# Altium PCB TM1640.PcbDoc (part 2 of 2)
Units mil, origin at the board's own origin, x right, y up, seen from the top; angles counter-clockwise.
Board outline 3858.42 x 1968.54 mil, 2 copper layers (Top Layer, Bottom Layer); 104 components, 33 nets, 245 pads, 113 vias.
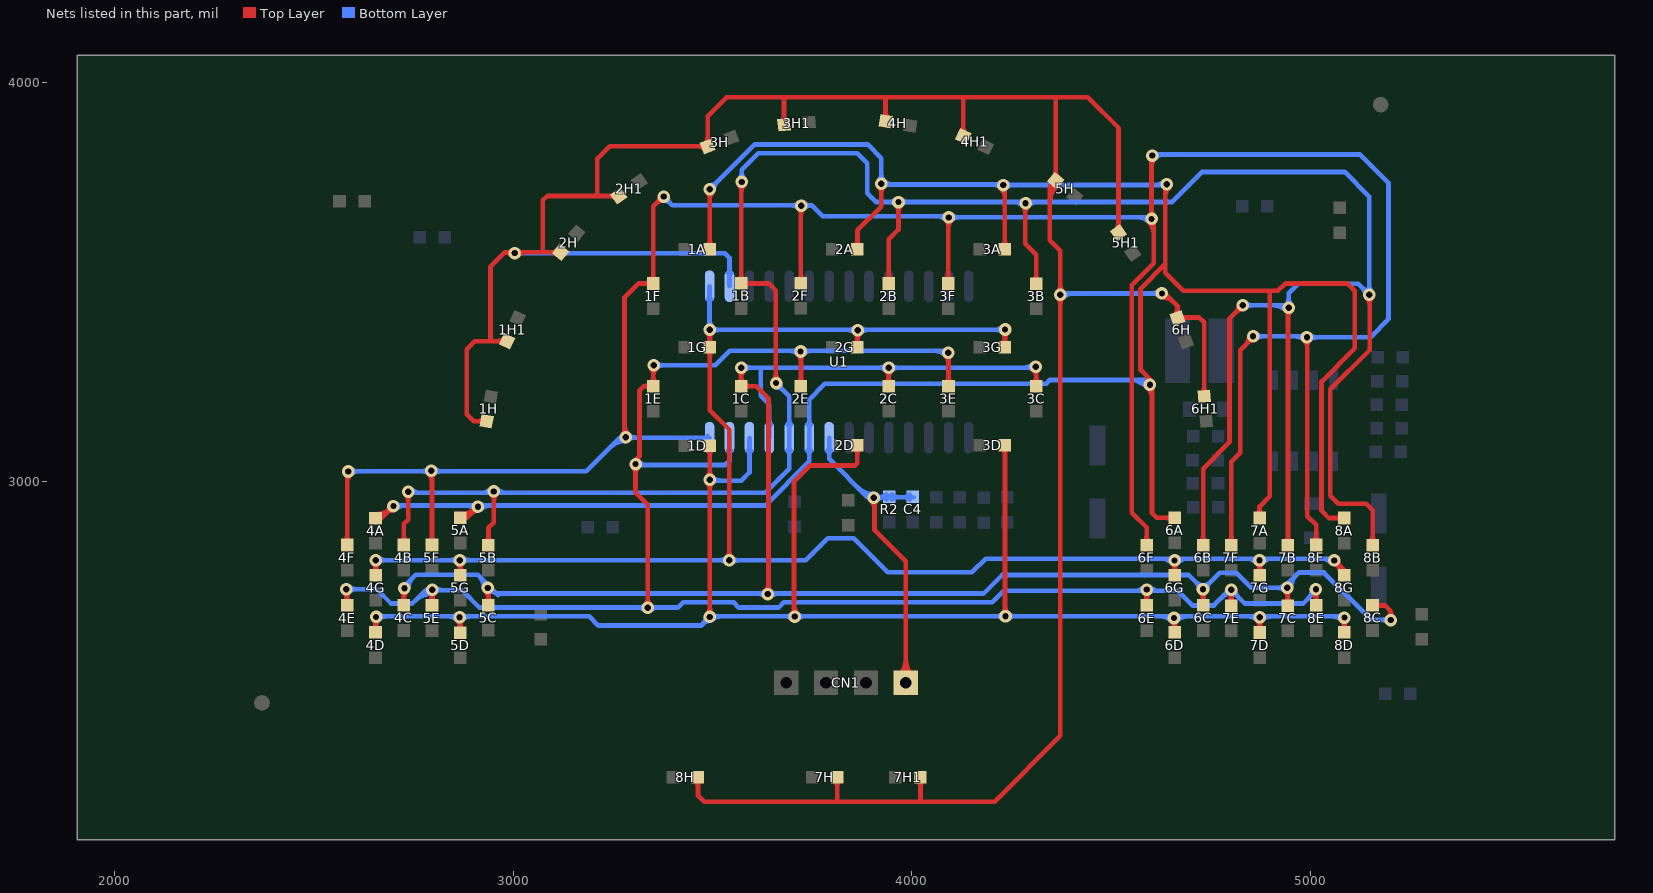
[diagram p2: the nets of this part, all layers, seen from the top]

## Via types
v1: diameter 31.5, hole 15.75, Top Layer to Bottom Layer, 113 vias

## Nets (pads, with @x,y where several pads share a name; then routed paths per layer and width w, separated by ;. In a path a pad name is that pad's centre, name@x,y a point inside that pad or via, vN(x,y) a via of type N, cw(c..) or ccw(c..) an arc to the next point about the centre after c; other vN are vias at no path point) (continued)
SCLK: C4.2 CN1.4 R2.1 U1.8 | length 1248.2
  Top Layer w11.81: v1@3897.21,2951.86 cw(c3875.75,2930.4) 3906.1,2930.4 ; 3906.1,2939.71 cw(c3923.28,2939.71) v1@3911.13,2951.86 ; v1@3906.1,2966.97 3906.1,2877.56 3984.44,2799.22 CN1.4@3984.44,2494.68 ; CN1.4@3967.18,2511.94 ccw(c3925.51,2553.61) 3984.44,2553.61 ccw(c4043.37,2553.61) CN1.4@4001.7,2511.94 ; CN1.4@3975.53,2503.59 ccw(c3954.03,2525.09) 3984.44,2525.09 ccw(c4014.86,2525.09) CN1.4@3993.35,2503.59
  Bottom Layer w11.81: U1.8@3787.82,3077.37 cw(c3777.41,3066.97) 3792.12,3066.97 ; 3792.13,3066.97 cw(c3806.84,3066.97) U1.8@3796.44,3077.37 ; U1.8@3792.13,3109.68 3792.13,3056.3 3888.15,2960.28 ; 3862.5,2985.92 ccw(c3904.17,3027.59) v1@3904.17,2968.66 ; 3882.67,2965.76 ccw(c3904.17,2987.26) v1@3904.17,2956.85 ; 3888.15,2960.27 cw(c3888.15,2953.11) v1@3894.9,2955.51 ; v1@3896.08,2964.43 cw(c3888.15,2969.93) 3888.15,2960.28 ; v1@3911.13,2951.86 cw(c3931.45,2931.54) R2.1@3931.45,2960.28 ; v1@3911.13,2965.78 ccw(c3924.42,2979.06) 3924.42,2960.28 ; v1@3916.93,2960.28 ccw(c3916.93,2987.13) R2.1@3935.91,2968.14 ; 3921.3,2960.27 cw(c3921.3,2939.6) R2.1@3935.91,2954.22 ; R2.1@3949.83,2954.22 cw(c3964.45,2939.6) 3964.45,2960.27 ; R2.1@3949.83,2968.14 ccw(c3968.82,2987.13) 3968.82,2960.28 ; 3975.7,2960.28 ccw(c3975.7,2987.13) C4.2@3994.69,2968.14 ; 3980.08,2960.28 cw(c3980.08,2939.61) C4.2@3994.69,2954.22 ; C4.2@4004.05,2960.28 3888.15,2960.28
  other v1: 3904.17,2958.82
SEG1: 1A.1 2A.1 3A.1 4A.1 5A.1 6A.1 7A.1 8A.1 U1.9 | length 7747.7
  Top Layer w11.81: 4A.1@2654.05,2906.14 ccw(c2654.05,2937.51) 2676.23,2915.33 ; 4A.1@2654.05,2908.11 2669.01,2908.11 v1(2698.98,2938.07) ; 4A.1@2654.05,2917.95 ccw(c2654.05,2977.83) v1@2696.4,2935.49 ; v1@2689.13,2938.07 cw(c2665.37,2938.07) 2682.17,2921.27 cw(c2698.98,2904.47) v1@2698.98,2928.23 ; 5A.1@2866.26,2906.46 ccw(c2866.88,2940.95) 2891.28,2916.56 ; 5A.1@2866.3,2908.43 2883.15,2908.43 ; 5A.1@2866.48,2918.27 ccw(c2867.58,2979.58) v1(2910.94,2936.22) 2883.15,2908.43 ; 5A.1@2874.87,2903.59 cw(c2883.15,2898.92) 2883.15,2908.42 ; 5A.1@2874.87,2913.26 ccw(c2883.15,2917.93) 2883.15,2908.43 ; v1@2901.1,2936.22 cw(c2877.34,2936.22) 2894.14,2919.42 cw(c2910.94,2902.62) v1@2910.94,2926.38 ; 1A.1@3485.95,3589.4 ccw(c3469.15,3606.2) 3492.91,3606.2 ccw(c3516.68,3606.2) 1A.1@3499.87,3589.4 ; v1@3485.95,3726.03 cw(c3469.15,3709.23) 3492.91,3709.23 cw(c3516.68,3709.23) v1@3499.87,3726.03 ; 1A.1@3492.91,3582.44 v1@3492.91,3729.33 ; 2A.1@3856.19,3589.4 ccw(c3839.39,3606.2) 3863.15,3606.2 ccw(c3886.91,3606.2) 2A.1@3870.11,3589.4 ; 2A.1@3863.15,3582.44 3863.15,3629.64 3923.19,3689.68 v1(3923.19,3746.97) ; v1@3916.23,3740.01 cw(c3899.43,3723.21) 3923.19,3723.21 cw(c3946.95,3723.21) v1@3930.15,3740.01 ; v1@4222.33,3736.5 cw(c4196.78,3710.96) 4232.91,3710.96 ; 3A.1@4225.95,3589.16 ccw(c4209.15,3605.97) 4232.91,3605.97 ccw(c4256.68,3605.97) 3A.1@4239.87,3589.16 ; 3A.1@4232.91,3582.2 v1@4232.91,3739.84 ; v1@4590.09,3235.8 cw(c4561.31,3207.02) 4602.01,3207.02 ; v1@4602.01,3242.76 4602.01,2921.06 4614.45,2908.62 6A.1@4659.65,2908.62 6A.1@4664.53,2903.74 ; v1@4602.01,3250.94 4573.39,3279.57 4573.39,3483.66 4635.24,3545.51 ; 4635.24,3712.43 cw(c4672.57,3712.43) v1@4646.17,3738.83 ; v1@4635.24,3744.33 4635.24,3545.51 ; 6A.1@4652.68,2901.66 ccw(c4635.88,2884.86) 4635.88,2908.62 ccw(c4635.88,2932.38) 6A.1@4652.68,2915.58 ; 7A.1@4865.05,2915.19 ccw(c4848.24,2931.99) 4872.01,2931.99 ccw(c4895.77,2931.99) 7A.1@4878.97,2915.19 ; 7A.1@4872.01,2908.23 4872.01,2936.81 4897.8,2962.6 4897.8,3478.35 ; 8A.1@5078,2901.27 ccw(c5061.2,2884.47) 5061.2,2908.23 ccw(c5061.2,2931.99) 8A.1@5078,2915.19 ; 8A.1@5084.96,2908.23 5045.63,2908.23 5027.56,2926.3 5027.56,3250.51 5111.1,3334.05 5111.1,3478.54 5093.19,3496.46 4936.26,3496.46 4918.15,3478.35 4897.8,3478.35 ; 4635.24,3545.51 4635.24,3523.7 4680.59,3478.35 4897.8,3478.35
  Bottom Layer w11.81: v1@2697.83,2939.53 3631.3,2939.53 3742.13,3050.35 U1.9@3742.13,3109.68 3742.13,3205.16 3781.65,3244.68 4336.26,3244.68 4346.06,3254.49 4585.31,3254.49 ; v1@2705.94,2931.11 cw(c2726.26,2910.79) 2726.26,2939.53 ; v1@2705.94,2945.03 ccw(c2719.22,2958.32) 2719.22,2939.53 ; 2879.2,2939.53 cw(c2879.2,2904.47) v1@2903.98,2929.26 ; 2895.17,2939.53 ccw(c2895.17,2952) v1@2903.98,2943.18 ; v1@2917.9,2929.26 cw(c2942.69,2904.47) 2942.69,2939.53 ; v1@2917.9,2943.18 ccw(c2926.72,2952) 2926.72,2939.53 ; v1(3492.91,3732.99) 3605.39,3845.47 3888.43,3845.47 3923.19,3810.71 v1@3923.19,3749.41 ; v1@3492.91,3742.84 ccw(c3492.91,3766.6) 3509.71,3749.79 ccw(c3526.52,3732.99) v1@3502.76,3732.99 ; U1.9@3737.82,3077.37 cw(c3727.41,3066.97) 3742.12,3066.97 ; U1.9@3737.82,3141.99 ccw(c3727.41,3152.4) 3742.12,3152.4 ; 3742.13,3066.97 cw(c3756.84,3066.97) U1.9@3746.44,3077.37 ; 3742.13,3152.4 ccw(c3756.84,3152.4) U1.9@3746.44,3141.99 ; v1@3916.23,3753.93 ccw(c3899.43,3770.73) 3923.19,3770.73 ccw(c3946.95,3770.73) 3930.15,3753.93 ccw(c3951.89,3775.67) 3951.89,3744.92 ; v1@3927.68,3744.92 v1@4229.29,3744.92 ; v1@3930.15,3740.01 cw(c3942.01,3728.15) 3942.01,3744.92 ; 4202.01,3744.92 cw(c4202.01,3716.18) v1@4222.33,3736.5 ; 4209.05,3744.92 ccw(c4209.05,3763.71) v1@4222.33,3750.42 ; v1(4229.29,3743.46) v1@4628.98,3743.46 ; v1@4236.25,3736.5 cw(c4253.05,3719.7) 4253.05,3743.46 cw(c4253.05,3767.23) v1@4236.25,3750.42 ; 4544.96,3254.49 cw(c4544.96,3190.67) v1@4590.09,3235.8 ; 4573.48,3254.49 cw(c4573.48,3219.18) v1@4598.44,3244.15 ; 4609.84,3743.47 ccw(c4609.84,3775.16) v1@4632.25,3752.75 ; 4621.06,3743.46 cw(c4621.06,3727.63) v1@4632.25,3738.83
  other v1: 4597.05,3242.76 4639.21,3745.79
SEG2: 1B.1 2B.1 3B.1 4B.1 5B.1 6B.1 7B.1 8B.1 U1.10 | length 8107.5
  Top Layer w11.81: 4B.1@2718.08,2847.43 ccw(c2701.28,2864.23) 2725.04,2864.23 ccw(c2748.8,2864.23) 4B.1@2732,2847.43 ; 4B.1@2725.04,2840.47 2725.04,2893.46 2735.98,2904.41 v1(2735.98,2974.29) ; v1@2729.02,2967.33 cw(c2712.22,2950.53) 2735.98,2950.53 cw(c2759.75,2950.53) v1@2742.94,2967.33 ; 5B.1@2930.48,2847.24 ccw(c2913.68,2864.04) 2937.44,2864.04 ccw(c2961.2,2864.04) 5B.1@2944.4,2847.24 ; 5B.1@2937.44,2840.28 2937.44,2883.43 2950.91,2896.89 v1(2950.91,2974.88) ; v1@2943.94,2967.92 cw(c2927.14,2951.12) 2950.9,2951.12 cw(c2974.67,2951.12) v1@2957.87,2967.92 ; 1B.1@3564.73,3503.73 ccw(c3547.93,3520.53) 3571.69,3520.53 ccw(c3595.45,3520.53) 3578.65,3503.73 ccw(c3595.45,3520.53) 3595.45,3496.77 ccw(c3595.45,3473.01) 1B.1@3578.65,3489.81 ; v1@3565.95,3744.46 cw(c3552.1,3730.6) 3571.69,3730.6 ; 3571.69,3724.71 cw(c3599.62,3724.71) v1@3579.87,3744.46 ; v1@3571.69,3753.46 1B.1@3571.69,3496.77 3640.08,3496.77 3657.87,3478.98 v1@3657.87,3246.1 ; v1@3651.94,3253.65 ccw(c3637.61,3267.98) 3657.87,3267.98 ; 3657.87,3272.93 ccw(c3685.13,3272.93) v1@3665.86,3253.65 ; 2B.1@3934.85,3503.46 ccw(c3918.05,3520.26) 3941.81,3520.26 ccw(c3965.57,3520.26) 2B.1@3948.77,3503.46 ; 2B.1@3941.81,3496.5 3941.81,3607.83 3966.14,3632.16 v1(3966.14,3700.87) ; v1@3959.18,3693.91 cw(c3942.38,3677.1) 3966.14,3677.1 cw(c3989.9,3677.1) v1@3973.1,3693.91 ; v1@4278.04,3691.03 cw(c4263.71,3676.7) 4283.97,3676.7 ; 4283.98,3671.76 cw(c4311.23,3671.76) v1@4291.96,3691.03 ; v1@4283.98,3698.54 4283.98,3596.85 4311.73,3569.09 3B.1@4311.73,3496.46 ; 3B.1@4304.77,3503.42 ccw(c4287.97,3520.22) 4311.73,3520.22 ccw(c4335.49,3520.22) 3B.1@4318.69,3503.42 ; 6B.1@4723.47,2847.2 ccw(c4706.67,2864) 4730.43,2864 ccw(c4754.19,2864) 6B.1@4737.39,2847.2 ; 6B.1@4730.43,2840.24 4730.43,3032.12 4796.53,3098.23 4796.53,3408.46 v1@4832.24,3444.17 ; 4812.74,3424.67 ccw(c4795.6,3441.81) v1@4819.84,3441.81 ; 4813.22,3425.15 cw(c4829.69,3408.68) v1@4829.69,3431.97 ; 7B.1@4936.15,2847.12 ccw(c4919.35,2863.92) 4943.11,2863.92 ccw(c4966.87,2863.92) 7B.1@4950.07,2847.12 ; v1@4938.04,3428.51 cw(c4925.8,3416.27) 4943.11,3416.27 ; 7B.1@4943.11,2840.16 v1@4943.11,3433.58 ; 4943.11,3407.15 cw(c4973.32,3407.15) v1@4951.96,3428.51 ; v1@5140.24,3461.27 cw(c5121.26,3442.28) 5148.11,3442.28 ; 5148.11,3446.65 cw(c5168.78,3446.65) v1@5154.16,3461.27 ; v1@5148.11,3467.36 5148.11,3329.72 5049.37,3230.98 5049.37,2964.49 5069.92,2943.94 5140,2943.94 5155.71,2928.23 8B.1@5155.71,2840.28 ; 8B.1@5148.75,2847.24 ccw(c5131.95,2864.04) 5155.71,2864.04 ccw(c5179.47,2864.04) 8B.1@5162.67,2847.24
  Bottom Layer w11.81: v1@2736.69,2971.38 3632.3,2971.38 3692.13,3031.2 U1.10@3692.13,3109.68 3692.13,3213.46 v1(3658.9,3246.69) ; v1@2742.94,2967.33 cw(c2752.71,2957.56) 2752.71,2971.38 ; v1@2742.94,2981.25 ccw(c2766.78,3005.09) 2766.78,2971.38 ; 2918.68,2971.38 ccw(c2918.68,3007.1) v1@2943.95,2981.84 ; v1@2957.86,2981.84 ccw(c2983.13,3007.1) 2983.13,2971.38 ; v1@3565.95,3758.38 ccw(c3549.15,3775.18) 3572.91,3775.18 ccw(c3596.68,3775.18) v1@3579.87,3758.38 ; v1(3572.91,3751.42) 3572.91,3782.15 3614.43,3823.66 3862.64,3823.66 3887.87,3798.43 3887.87,3722.91 3909.92,3700.87 v1(3966.14,3700.87) 4652.24,3700.87 4727.72,3776.34 5085.47,3776.34 5147.2,3714.61 v1(5147.2,3468.23) 5119.33,3496.1 4968.58,3496.1 4945,3472.52 v1(4945,3435.47) ; v1@3658.9,3236.85 cw(c3658.9,3213.09) 3675.7,3229.89 cw(c3692.5,3246.69) v1@3668.74,3246.69 ; U1.10@3687.82,3077.37 cw(c3677.41,3066.97) 3692.12,3066.97 ; U1.10@3687.82,3141.99 ccw(c3677.41,3152.4) 3692.12,3152.4 ; 3692.13,3066.97 cw(c3706.84,3066.97) U1.10@3696.44,3077.37 ; 3692.13,3152.4 ccw(c3706.84,3152.4) U1.10@3696.44,3141.99 ; v1@3959.18,3693.91 ccw(c3942.38,3677.1) 3942.38,3700.86 ccw(c3942.38,3724.63) v1@3959.18,3707.83 ; v1@3973.1,3693.91 cw(c3989.9,3677.1) 3989.9,3700.86 cw(c3989.9,3724.63) v1@3973.1,3707.83 ; 4254.3,3700.87 cw(c4254.3,3667.29) v1@4278.04,3691.03 ; 4268.18,3700.87 ccw(c4268.18,3714.82) v1@4278.04,3704.95 ; v1@4291.96,3691.03 cw(c4315.7,3667.29) 4315.7,3700.87 ; v1@4291.96,3704.95 ccw(c4301.82,3714.82) 4301.82,3700.87 ; v1(4829.69,3441.81) v1@4943.98,3441.81 ; v1@4836.65,3434.85 cw(c4853.45,3418.05) 4853.45,3441.81 cw(c4853.45,3465.57) v1@4836.65,3448.77 ; 4905.94,3441.81 cw(c4905.94,3396.41) v1@4938.04,3428.51 ; v1@4938.04,3442.43 ccw(c4921.24,3459.23) 4945,3459.23 ccw(c4968.76,3459.23) v1@4951.96,3442.43 ; v1@5137.36,3468.23 ccw(c5113.6,3468.23) 5130.4,3485.03 ccw(c5147.2,3501.83) v1@5147.2,3478.07 ; v1@5140.24,3475.19 ccw(c5123.44,3491.99) 5147.2,3491.99 ccw(c5170.97,3491.99) v1@5154.16,3475.19
  other v1: 4285,3697.99
SEG3: 1C.1 2C.1 3C.1 4C.1 5C.1 6C.1 7C.1 8C.1 U1.11 | length 5695.8
  Top Layer w11.81: 4C.1@2717.72,2695.86 ccw(c2700.92,2712.66) 2724.68,2712.66 ccw(c2748.45,2712.66) 4C.1@2731.64,2695.86 ; v1@2719.58,2724.81 cw(c2707.24,2712.48) 2724.68,2712.48 ; 4C.1@2724.68,2688.9 v1@2724.68,2729.92 ; 4C.1@2724.68,2703.54 cw(c2754.76,2703.54) v1@2733.5,2724.81 ; v1@2928.9,2725.72 cw(c2908.3,2705.11) 2937.44,2705.11 ; 5C.1@2930.48,2696.02 ccw(c2913.68,2712.82) 2937.44,2712.82 ccw(c2961.2,2712.82) 5C.1@2944.4,2696.02 ; 5C.1@2937.44,2689.05 v1@2937.44,2731.1 ; 2937.44,2712.72 cw(c2955.83,2712.72) v1@2942.83,2725.72 ; 1C.1@3564.5,3245.86 ccw(c3547.69,3262.66) 3571.45,3262.66 ccw(c3595.22,3262.66) 3578.42,3245.86 ccw(c3595.22,3262.66) 3595.22,3238.9 ccw(c3595.22,3215.14) 1C.1@3578.42,3231.94 ; v1@3564.81,3278.39 cw(c3548.77,3262.35) 3571.46,3262.35 ; 3571.46,3260.83 cw(c3596.29,3260.83) v1@3578.73,3278.39 ; v1@3571.46,3281.97 1C.1@3571.46,3238.9 3608.9,3238.9 3640.24,3207.56 v1@3640.24,2723.15 ; v1@3631.39,2724.28 ccw(c3610.02,2745.65) 3640.24,2745.65 ; 3640.24,2736.52 ccw(c3657.55,2736.52) v1@3645.31,2724.28 ; v1@3934.46,3277.96 cw(c3917.37,3260.87) 3941.53,3260.87 ; 2C.1@3934.57,3245.74 ccw(c3917.77,3262.54) 3941.53,3262.54 ccw(c3965.3,3262.54) 2C.1@3948.5,3245.74 ; 2C.1@3941.53,3238.78 v1@3941.53,3284.8 ; 3941.53,3261.44 cw(c3964.89,3261.44) v1@3948.38,3277.96 ; v1@4303.2,3280.6 cw(c4282.31,3259.71) 4311.85,3259.71 ; 3C.1@4304.89,3245.86 ccw(c4288.09,3262.66) 4311.85,3262.66 ccw(c4335.61,3262.66) 3C.1@4318.81,3245.86 ; 3C.1@4311.85,3238.9 v1@4311.85,3285.87 ; 4311.85,3267.88 cw(c4329.83,3267.88) v1@4317.12,3280.6 ; v1@4723.2,2722.25 cw(c4705.92,2704.97) 4730.35,2704.97 ; 6C.1@4723.39,2695.86 ccw(c4706.59,2712.66) 4730.35,2712.66 ccw(c4754.12,2712.66) 6C.1@4737.31,2695.86 ; 6C.1@4730.35,2688.9 v1@4730.35,2723.11 ; 4730.35,2705.93 cw(c4753.44,2705.93) v1@4737.12,2722.25 ; v1@4934.3,2726.15 cw(c4913.79,2705.64) 4942.79,2705.64 ; 7C.1@4935.83,2695.54 ccw(c4919.03,2712.34) 4942.79,2712.34 ccw(c4966.56,2712.34) 7C.1@4949.76,2695.54 ; 7C.1@4942.8,2688.58 v1@4942.8,2733.07 ; 4942.79,2713.05 cw(c4961.31,2713.05) v1@4948.22,2726.15 ; 8C.1@5155.39,2688.9 5186.69,2688.9 5201.14,2674.45 ; 8C.1@5162.35,2681.94 cw(c5179.15,2665.14) 5179.15,2688.9 cw(c5179.15,2712.66) 8C.1@5162.35,2695.86 ; v1@5194.53,2659.54 ccw(c5181.02,2674.45) 5201.14,2674.45 ; v1(5201.14,2652.24) 5201.14,2674.45 ; v1@5207.75,2659.54 cw(c5221.26,2674.45) 5201.14,2674.45
  Bottom Layer w11.81: v1@2723.9,2734.41 2755.59,2766.1 2910.59,2766.1 2957.91,2718.78 4179.49,2718.78 4225.94,2765.24 4694.13,2765.24 v1(4730.16,2729.21) 4771.85,2770.91 4813.35,2770.91 4851.14,2733.11 v1(4941.26,2733.11) ; v1@2736.38,2731.77 cw(c2772.88,2731.77) 2747.07,2757.58 ; 2913.3,2763.39 cw(c2882.59,2732.68) v1@2926.02,2732.68 ; v1@2937.27,2722.93 cw(c2941.41,2694.12) 2961.99,2714.71 ; v1(3571.77,3285.35) 3620.55,3285.35 ; v1@3578.73,3278.39 cw(c3595.53,3261.59) 3595.53,3285.35 cw(c3595.53,3309.12) v1@3578.73,3292.31 ; 3611.07,2718.78 cw(c3611.07,2690.04) v1@3631.39,2710.36 ; 3618.1,2718.78 ccw(c3618.1,2737.57) v1@3631.39,2724.28 ; U1.11@3637.82,3141.99 ccw(c3627.41,3152.4) 3642.12,3152.4 ; U1.11@3642.13,3109.68 3642.13,3193.39 3620.55,3214.96 3620.55,3285.35 ; 3642.13,3152.4 ccw(c3656.84,3152.4) U1.11@3646.44,3141.99 ; v1@3645.31,2710.36 cw(c3665.62,2690.04) 3665.62,2718.78 ; v1@3645.31,2724.28 ccw(c3658.59,2737.57) 3658.59,2718.78 ; 3916.61,3285.35 cw(c3916.61,3260.11) v1@3934.46,3277.96 ; 3918.7,3285.35 ccw(c3918.7,3307.64) v1@3934.46,3291.88 ; v1@3948.38,3277.96 cw(c3966.22,3260.11) 3966.22,3285.35 ; v1@3948.38,3291.88 ccw(c3964.13,3307.64) 3964.13,3285.35 ; 4281.07,3285.35 ccw(c4281.07,3316.64) v1@4303.2,3294.52 ; 4291.72,3285.35 cw(c4291.72,3269.12) v1@4303.2,3280.6 ; v1@4309.25,3285.35 3620.55,3285.35 ; v1@4720.31,2729.21 ccw(c4696.55,2729.21) 4713.35,2746.01 ccw(c4730.16,2762.82) 4730.16,2739.06 ccw(c4730.16,2762.82) 4746.96,2746.02 ccw(c4763.76,2729.21) v1@4740,2729.21 ; v1@4934.3,2726.15 ccw(c4917.5,2709.35) 4917.5,2733.11 ccw(c4917.5,2756.87) v1@4934.3,2740.07 ; v1@4936.48,2737.89 4969.96,2771.38 5033.5,2771.38 5151.85,2653.03 v1@5201.14,2653.03 ; v1@4951.1,2733.11 cw(c4997.96,2733.11) 4964.83,2766.24 ; 5175.48,2653.03 cw(c5175.48,2626.58) v1@5194.18,2645.28 ; 5179.28,2653.03 ccw(c5179.28,2674.11) v1@5194.18,2659.2
  other v1: 3638.35,2717.32 2726.53,2731.77 2935.87,2732.68 3941.42,3284.92 4310.16,3287.56
SEG4: 1D.1 2D.1 3D.1 4D.1 5D.1 6D.1 7D.1 8D.1 U1.12 | length 5477.5
  Top Layer w11.81: 4D.1@2647.09,2627.98 ccw(c2630.29,2644.78) 2654.05,2644.78 ccw(c2677.82,2644.78) 4D.1@2661.01,2627.98 ; v1@2648.47,2653.08 cw(c2635,2639.6) 2654.05,2639.6 ; 4D.1@2654.05,2621.02 v1@2654.05,2658.66 ; 4D.1@2654.05,2632.95 cw(c2682.52,2632.95) v1@2662.39,2653.08 ; v1@2857.88,2652.25 cw(c2836.42,2630.79) 5D.1@2866.77,2630.79 ; 5D.1@2859.81,2627.79 ccw(c2843.01,2644.59) 2866.77,2644.59 ccw(c2890.53,2644.59) 5D.1@2873.73,2627.79 ; 5D.1@2866.77,2620.83 v1@2866.77,2657.28 ; 2866.77,2640.11 cw(c2883.95,2640.11) v1@2871.8,2652.25 ; v1@3485.68,2667 ccw(c3468.59,2684.09) 3492.76,2684.09 ; v1@3485.68,2997.05 cw(c3468.59,2979.97) 3492.76,2979.97 ; v1@3485.68,3010.98 ccw(c3468.59,3028.06) 3492.76,3028.06 ; 1D.1@3485.8,3083.04 cw(c3468.99,3066.24) 3492.76,3066.24 cw(c3516.52,3066.24) 1D.1@3499.72,3083.04 ; v1@3492.76,2661.14 1D.1@3492.76,3090 ; 3492.76,2683.52 ccw(c3516.11,2683.52) v1@3499.6,2667 ; 3492.76,2980.54 cw(c3516.11,2980.54) v1@3499.6,2997.06 ; 3492.76,3027.49 ccw(c3516.11,3027.49) v1@3499.6,3010.97 ; v1@3699.18,2667.83 ccw(c3687.7,2679.3) 3703.94,2679.3 ; v1@3703.94,2660.98 3703.94,2999.64 3743.98,3039.68 3856.89,3039.68 3862.99,3045.79 2D.1@3862.99,3090.43 ; 3703.94,2689.95 ccw(c3735.23,2689.95) v1@3713.1,2667.83 ; 2D.1@3856.03,3083.47 cw(c3839.23,3066.67) 3862.99,3066.67 cw(c3886.75,3066.67) 2D.1@3869.95,3083.47 ; 3D.1@4226.15,3083.31 cw(c4209.35,3066.51) 4233.11,3066.51 cw(c4256.87,3066.51) 3D.1@4240.07,3083.31 ; v1@4227.65,2668.65 ccw(c4214.46,2681.84) 4233.11,2681.84 ; v1@4233.11,2663.54 3D.1@4233.11,3090.28 ; 4233.11,2689.07 ccw(c4261.98,2689.07) v1@4241.57,2668.65 ; v1@4650.4,2650.36 cw(c4628.56,2628.52) 6D.1@4659.45,2628.52 ; 6D.1@4652.49,2627.98 ccw(c4635.69,2644.78) 4659.45,2644.78 ccw(c4683.21,2644.78) 6D.1@4666.41,2627.98 ; 6D.1@4659.45,2621.02 v1@4659.45,2655.24 ; 4659.45,2638.6 cw(c4676.09,2638.6) v1@4664.32,2650.36 ; 7D.1@4865.28,2627.9 ccw(c4848.48,2644.71) 4872.24,2644.71 ccw(c4896.01,2644.71) 7D.1@4879.2,2627.9 ; v1@4865.28,2652.25 cw(c4848.48,2635.45) 4872.24,2635.45 cw(c4896.01,2635.45) v1@4879.2,2652.25 ; 7D.1@4872.24,2620.94 v1(4872.24,2659.21) ; 8D.1@5077.72,2627.98 ccw(c5060.92,2644.78) 5084.68,2644.78 ccw(c5108.45,2644.78) 8D.1@5091.64,2627.98 ; v1@5077.96,2651.46 cw(c5061.73,2635.23) 8D.1@5084.68,2635.23 ; 8D.1@5084.68,2621.02 v1@5084.68,2658.19 ; 8D.1@5084.68,2634.09 cw(c5109.25,2634.09) v1@5091.88,2651.46
  Bottom Layer w11.81: v1@2656.81,2661.69 3189.88,2661.69 3213.15,2638.43 3471.02,2638.43 v1(3492.64,2660.04) ; v1@2662.39,2653.08 cw(c2683.19,2632.28) 2683.19,2661.69 ; v1@2662.39,2667 ccw(c2675.2,2679.81) 2675.2,2661.69 ; 2835.09,2661.69 cw(c2835.09,2629.46) v1@2857.88,2652.25 ; 2847.07,2661.69 ccw(c2847.07,2676.99) v1@2857.88,2666.17 ; v1@2871.8,2652.25 cw(c2894.59,2629.46) 2894.59,2661.69 ; v1@2871.8,2666.17 ccw(c2882.62,2676.99) 2882.62,2661.69 ; v1@3482.79,2660.04 cw(c3459.03,2660.04) 3475.83,2643.24 cw(c3492.64,2626.43) v1@3492.64,2650.2 ; v1@3492.64,2661.69 v1(4234.61,2661.69) v1@5081.34,2661.69 ; v1@3495.35,3001.69 3571.46,3001.69 3592.13,3022.36 U1.12@3592.13,3109.68 ; v1@3499.6,2653.08 cw(c3520.39,2632.28) 3520.39,2661.69 ; v1@3499.6,2667 ccw(c3512.41,2679.81) 3512.41,2661.69 ; v1@3499.6,2997.06 cw(c3510.79,2985.86) 3510.79,3001.69 ; v1@3499.6,3010.98 ccw(c3522.01,3033.39) 3522.01,3001.69 ; U1.12@3587.82,3077.37 cw(c3577.41,3066.97) 3592.12,3066.97 ; 3592.13,3066.97 cw(c3606.84,3066.97) U1.12@3596.44,3077.37 ; 3680.38,2661.69 cw(c3680.38,2635.11) v1@3699.18,2653.91 ; 3684.38,2661.69 ccw(c3684.38,2682.63) v1@3699.18,2667.82 ; v1@3713.1,2653.91 cw(c3731.9,2635.11) 3731.9,2661.69 ; v1@3713.1,2667.82 ccw(c3727.91,2682.63) 3727.91,2661.69 ; v1@4227.65,2654.73 ccw(c4210.84,2637.93) 4210.84,2661.69 ccw(c4210.84,2685.45) v1@4227.65,2668.65 ; v1@4241.57,2654.73 cw(c4258.37,2637.93) 4258.37,2661.69 cw(c4258.37,2685.45) v1@4241.57,2668.65 ; 4623.05,2661.69 cw(c4623.05,2623.01) v1@4650.4,2650.36 ; v1@4664.32,2650.36 cw(c4691.67,2623.01) 4691.67,2661.69 ; 4842.49,2661.69 cw(c4842.49,2629.46) v1@4865.28,2652.25 ; 4854.47,2661.69 ccw(c4854.47,2676.99) v1@4865.28,2666.17 ; v1@4879.2,2652.25 cw(c4901.99,2629.46) 4901.99,2661.69 ; v1@4879.2,2666.17 ccw(c4890.02,2676.99) 4890.02,2661.69 ; 5053.27,2661.69 cw(c5053.27,2626.77) v1@5077.96,2651.46 ; 5069.05,2661.69 ccw(c5069.05,2674.3) v1@5077.96,2665.38
  other v1: 4657.36,2657.32 5084.92,2658.43 2864.84,2659.21 2655.43,2660.04 3706.14,2660.87 3492.64,3004.01
SEG5: 1E.1 2E.1 3E.1 4E.1 5E.1 6E.1 7E.1 8E.1 U1.13 | length 6010.4
  Top Layer w11.81: v1@2574.02,2722.61 cw(c2552.47,2701.05) 4E.1@2582.95,2701.05 ; 4E.1@2575.99,2695.78 ccw(c2559.19,2712.58) 2582.95,2712.58 ccw(c2606.71,2712.58) 4E.1@2589.91,2695.78 ; 4E.1@2582.95,2688.82 v1@2582.95,2732.09 ; 2582.95,2710.56 cw(c2599.99,2710.56) v1@2587.94,2722.61 ; 5E.1@2788.75,2695.78 ccw(c2771.95,2712.58) 2795.71,2712.58 ccw(c2819.47,2712.58) 5E.1@2802.67,2695.78 ; v1@2789.34,2721.35 cw(c2773.96,2705.97) 2795.71,2705.97 ; 5E.1@2795.71,2688.82 v1@2795.71,2727.72 ; 5E.1@2795.71,2703.12 cw(c2821.49,2703.12) v1@2803.26,2721.35 ; v1@3299.46,3036.46 cw(c3282.66,3019.66) 3306.42,3019.66 cw(c3330.18,3019.66) v1@3313.38,3036.46 ; v1@3301.5,3048.35 3316.26,3063.11 ; v1(3306.42,3043.43) 3306.42,2971.93 3337.09,2941.26 v1@3337.09,2693.31 ; v1@3314.7,3048.74 cw(c3324.41,3054.96) 3316.26,3063.11 ; v1@3330.05,2689.95 ccw(c3313.06,2706.94) 3337.09,2706.94 ; 3337.09,2706.56 ccw(c3360.58,2706.56) v1@3343.97,2689.95 ; 1E.1@3344.1,3232.05 ccw(c3327.3,3215.25) 3327.3,3239.01 ccw(c3327.3,3262.78) 3344.1,3245.98 ccw(c3327.3,3262.78) 3351.06,3262.78 ccw(c3374.82,3262.78) 1E.1@3358.02,3245.98 ; v1@3345.01,3284.18 cw(c3330.39,3269.57) 3351.06,3269.57 ; 3351.06,3265.19 cw(c3377.92,3265.19) v1@3358.93,3284.18 ; v1@3351.06,3296.26 1E.1@3351.06,3239.01 3327.24,3239.01 3316.26,3228.03 3316.26,3063.11 ; v1@3713.51,3318.94 cw(c3694.43,3299.86) 3721.42,3299.86 ; 2E.1@3714.46,3245.7 ccw(c3697.66,3262.5) 3721.42,3262.5 ccw(c3745.18,3262.5) 2E.1@3728.38,3245.7 ; 2E.1@3721.42,3238.74 v1@3721.42,3324.96 ; 3721.42,3304.42 cw(c3741.95,3304.42) v1@3727.43,3318.95 ; v1@4083.67,3316.07 cw(c4064.68,3297.08) 4091.53,3297.08 ; 3E.1@4084.57,3245.7 ccw(c4067.77,3262.5) 4091.53,3262.5 ccw(c4115.3,3262.5) 3E.1@4098.5,3245.7 ; 3E.1@4091.53,3238.74 v1@4091.53,3322.13 ; 4091.54,3301.45 cw(c4112.21,3301.45) v1@4097.59,3316.07 ; 6E.1@4581.78,2695.78 ccw(c4564.98,2712.58) 4588.74,2712.58 ccw(c4612.5,2712.58) 6E.1@4595.7,2695.78 ; v1@4582.25,2721.78 cw(c4566.59,2706.12) 4588.74,2706.12 ; 6E.1@4588.74,2688.82 v1@4588.74,2728.27 ; 6E.1@4588.74,2703.84 cw(c4614.11,2703.84) v1@4596.17,2721.78 ; v1@4793.71,2721.39 cw(c4775.29,2702.97) 7E.1@4801.34,2702.97 ; 7E.1@4794.38,2695.58 ccw(c4777.58,2712.38) 4801.34,2712.38 ccw(c4825.1,2712.38) 7E.1@4808.3,2695.58 ; 7E.1@4801.34,2688.62 v1@4801.34,2727.68 ; 4801.34,2706.2 cw(c4822.81,2706.2) v1@4807.63,2721.39 ; v1@5006.39,2722.61 cw(c4988.54,2704.76) 5013.78,2704.76 ; 8E.1@5006.82,2695.78 ccw(c4990.02,2712.58) 5013.78,2712.58 ccw(c5037.54,2712.58) 8E.1@5020.74,2695.78 ; 8E.1@5013.78,2688.82 v1@5013.78,2729.13 ; 5013.78,2706.85 cw(c5036.06,2706.85) v1@5020.31,2722.61
  Bottom Layer w11.81: v1(2580.98,2729.57) 2657.05,2729.57 2692.91,2693.7 2746.5,2693.7 2780.04,2727.24 ; v1@2587.94,2722.61 cw(c2604.75,2705.8) 2604.75,2729.57 cw(c2604.75,2753.33) v1@2587.94,2736.53 ; 2753.55,2700.76 cw(c2796.3,2658.01) v1@2796.3,2718.46 ; 2772.44,2719.64 cw(c2781.84,2710.25) v1@2790.15,2720.62 ; 2773.72,2720.92 cw(c2796.3,2698.34) v1@2796.3,2730.28 ; v1@2787.19,2732.04 cw(c2780.04,2734.97) 2780.04,2727.24 ; v1@2788.07,2722.91 ccw(c2780.04,2717.64) 2780.04,2727.24 ; v1@2803.26,2721.35 cw(c2817.49,2707.11) 2817.49,2727.24 ; v1@2803.26,2735.27 ccw(c2822.63,2754.64) 2822.63,2727.24 ; v1@3311.3,3041.38 3531.38,3041.38 3542.13,3052.13 U1.13@3542.13,3109.68 ; 3312.01,2683.5 cw(c3312.01,2657.99) v1@3330.05,2676.03 ; v1@3313.38,3036.46 cw(c3325.24,3024.61) 3325.24,3041.38 ; v1@3313.38,3050.38 ccw(c3335.12,3072.13) 3335.12,3041.38 ; 3314.48,2683.5 ccw(c3314.48,2705.52) v1@3330.05,2689.95 ; v1@3343.97,2676.03 cw(c3362.01,2657.99) 3362.01,2683.5 ; v1@3343.97,2689.95 ccw(c3359.53,2705.52) 3359.53,2683.5 ; v1(3351.97,3291.14) 3506.26,3291.14 3542.8,3327.68 v1@4094.57,3327.68 ; v1@3358.93,3284.18 cw(c3375.73,3267.38) 3375.73,3291.14 cw(c3375.73,3314.9) v1@3358.93,3298.1 ; U1.13@3537.82,3077.37 cw(c3527.41,3066.97) 3542.12,3066.97 ; 3542.13,3066.97 cw(c3556.84,3066.97) U1.13@3546.44,3077.37 ; 3692.43,3327.68 cw(c3692.43,3297.87) v1@3713.51,3318.94 ; 3700.99,3327.68 ccw(c3700.99,3345.39) v1@3713.51,3332.87 ; v1@3727.43,3318.94 cw(c3748.51,3297.87) 3748.51,3327.68 ; v1@3727.43,3332.87 ccw(c3739.96,3345.39) 3739.96,3327.68 ; 4055.65,3327.68 cw(c4055.65,3288.05) v1@4083.67,3316.07 ; 4557.94,2725.63 ccw(c4557.94,2760.01) v1@4582.25,2735.7 ; 4572.96,2725.63 cw(c4572.96,2712.49) v1@4582.25,2721.78 ; v1@4596.17,2721.78 cw(c4605.47,2712.49) 4605.47,2725.63 ; v1@4596.17,2735.7 ccw(c4620.48,2760.01) 4620.48,2725.63 ; 4777.75,2709.01 cw(c4800.67,2686.09) 4800.67,2718.5 cw(c4800.67,2694.74) 4817.47,2711.54 cw(c4834.27,2728.35) v1@4810.51,2728.35 ; 4786.4,2717.66 ccw(c4775.71,2728.35) v1@4790.83,2728.35 ; v1(4800.67,2728.35) 4835.31,2693.7 4981.65,2693.7 v1@5014.8,2726.85 ; v1@4800.67,2728.9 4797.64,2728.9 4757.56,2688.82 4703.54,2688.82 4666.73,2725.63 4230.08,2725.63 4201.42,2696.97 3678.58,2696.97 3665.12,2683.5 3565.71,2683.5 3552.24,2696.97 3425.83,2696.97 3412.36,2683.5 2914.96,2683.5 2871.22,2727.24 2780.04,2727.24 ; 4993.59,2705.64 ccw(c4969.67,2729.57) v1@5003.5,2729.57 ; 5003.67,2715.72 cw(c5013.35,2706.04) v1@5013.35,2719.72
  other v1: 3337.01,2682.99 2796.3,2728.31 4589.21,2728.74 5013.35,2729.57 4090.63,3323.03 3720.47,3325.91
SEG6: 1F.1 2F.1 3F.1 4F.1 5F.1 6F.1 7F.1 8F.1 U1.14 | length 8315.4
  Top Layer w11.81: 4F.1@2576.07,2847.47 ccw(c2559.27,2864.27) 2583.03,2864.27 ccw(c2606.79,2864.27) 4F.1@2589.99,2847.47 ; v1@2578.55,3017.96 cw(c2567.74,3007.15) 2583.03,3007.15 ; 4F.1@2583.03,2840.51 v1@2583.03,3022.44 ; 2583.03,2995.17 cw(c2615.26,2995.17) v1@2592.47,3017.96 ; v1@2787.25,3019.58 cw(c2766.55,2998.88) 2795.83,2998.88 ; 5F.1@2788.87,2847.47 ccw(c2772.06,2864.27) 2795.82,2864.27 ; 5F.1@2795.83,2840.51 v1@2795.83,3024.92 ; 2795.83,2864.27 ccw(c2819.59,2864.27) 5F.1@2802.79,2847.47 ; 2795.83,3006.67 cw(c2814.08,3006.67) v1@2801.17,3019.58 ; v1@3274.77,3118.1 ccw(c3265.1,3127.77) 3278.78,3127.77 ; v1@3278.78,3119.21 3278.78,3461.69 3313.58,3496.5 1F.1@3350.91,3496.5 3350.91,3690.16 v1@3375.39,3714.64 ; 3278.78,3142.03 ccw(c3312.62,3142.03) v1@3288.69,3118.1 ; 1F.1@3343.94,3489.54 ccw(c3327.14,3472.73) 3327.14,3496.49 ccw(c3327.14,3520.26) 3343.94,3503.46 ccw(c3327.14,3520.26) 3350.9,3520.26 ccw(c3374.67,3520.26) 1F.1@3357.87,3503.46 ; 3357.54,3696.8 cw(c3376.97,3677.37) v1@3376.97,3704.84 ; 3361.25,3700.5 ccw(c3347.07,3714.68) v1@3367.12,3714.68 ; 2F.1@3714.18,3503.85 ccw(c3697.38,3520.65) 3721.14,3520.65 ccw(c3744.9,3520.65) 2F.1@3728.1,3503.85 ; v1@3715.13,3684.77 cw(c3700.61,3670.25) 3721.14,3670.25 ; 2F.1@3721.14,3496.89 v1@3721.14,3690.79 ; 3721.14,3665.69 cw(c3748.13,3665.69) v1@3729.05,3684.77 ; 3F.1@4084.34,3503.46 ccw(c4067.54,3520.26) 4091.3,3520.26 ccw(c4115.06,3520.26) 3F.1@4098.26,3503.46 ; v1@4085.24,3655.44 cw(c4070.63,3640.83) 4091.3,3640.83 ; 3F.1@4091.3,3496.5 v1@4091.3,3661.49 ; 4091.3,3636.45 cw(c4118.15,3636.45) v1@4099.16,3655.44 ; 6F.1@4581.7,2847.16 ccw(c4564.9,2863.96) 4588.66,2863.96 ccw(c4612.42,2863.96) 6F.1@4595.62,2847.16 ; 6F.1@4588.66,2840.2 4588.66,2884.37 4551.57,2921.46 4551.57,3492.7 4606.34,3547.46 v1@4606.34,3662.13 ; v1@4594.18,3651.54 cw(c4564.83,3622.2) 4606.34,3622.2 ; v1@4594.18,3665.46 ccw(c4577.38,3682.26) 4601.14,3682.26 ccw(c4624.9,3682.26) v1@4608.1,3665.46 ; v1@4595.76,3810.52 cw(c4582.76,3797.52) 4601.14,3797.52 ; v1(4601.14,3658.5) v1@4601.14,3815.91 ; 4601.14,3789.92 cw(c4630.28,3789.92) v1@4609.68,3810.52 ; 7F.1@4794.38,2847.27 ccw(c4777.58,2864.08) 4801.34,2864.08 ccw(c4825.1,2864.08) 7F.1@4808.3,2847.27 ; 7F.1@4801.34,2840.32 4801.34,3049.09 4823.66,3071.42 4823.66,3329.49 v1@4857.03,3362.85 ; 4837.23,3343.06 ccw(c4816.19,3364.09) v1@4845.94,3364.09 ; 4843.22,3349.05 cw(c4855.79,3336.48) v1@4855.79,3354.25 ; v1@4983.87,3354.65 cw(c4964.88,3335.67) 4991.73,3335.67 ; 4991.73,3340.04 cw(c5012.4,3340.04) v1@4997.79,3354.65 ; v1@4991.73,3365.08 4991.73,2913.19 5013.9,2891.02 8F.1@5013.9,2840.51 ; 8F.1@5006.94,2847.47 ccw(c4990.14,2864.27) 5013.9,2864.27 ccw(c5037.66,2864.27) 8F.1@5020.86,2847.47
  Bottom Layer w11.81: v1@2592.47,3017.96 cw(c2610.13,3000.3) 2610.13,3025.27 ; v1@2592.47,3031.88 ccw(c2608.42,3047.83) 2608.42,3025.28 ; v1@2598.62,3025.28 3182.8,3025.28 3267.2,3109.68 U1.14@3492.13,3109.68 ; 2767.41,3025.28 ccw(c2767.41,3053.34) v1@2787.25,3033.49 ; 2773.49,3025.27 cw(c2773.49,3005.81) v1@2787.25,3019.57 ; v1@2801.17,3019.57 cw(c2814.93,3005.81) 2814.93,3025.27 ; v1@2801.17,3033.49 ccw(c2821.02,3053.34) 2821.02,3025.28 ; 3242.62,3085.1 cw(c3281.73,3045.98) v1@3281.73,3101.3 ; 3262.78,3105.26 cw(c3281.73,3086.31) v1@3281.73,3113.11 ; v1@3288.69,3104.18 cw(c3301.98,3090.9) 3301.98,3109.68 ; v1@3288.69,3118.1 ccw(c3309.01,3138.42) 3309.01,3109.68 ; v1@3376.97,3704.84 cw(c3376.97,3681.08) 3393.77,3697.88 cw(c3410.57,3714.68) v1@3386.81,3714.68 ; v1(3376.97,3714.68) 3399.09,3692.56 3748.54,3692.56 3775.55,3665.55 v1@4092.72,3665.55 ; U1.14@3487.82,3105.37 ccw(c3477.41,3094.97) 3477.41,3109.68 ccw(c3477.41,3124.4) U1.14@3487.82,3113.99 ; 3696.33,3692.56 cw(c3696.33,3665.97) v1@3715.13,3684.77 ; 3700.32,3692.56 ccw(c3700.32,3713.5) v1@3715.13,3698.69 ; v1@3729.05,3684.77 cw(c3747.84,3665.97) 3747.84,3692.56 ; v1@3729.05,3698.69 ccw(c3743.85,3713.5) 3743.85,3692.56 ; 4060.84,3665.55 cw(c4060.84,3631.03) v1@4085.24,3655.44 ; 4076.05,3665.55 ccw(c4076.05,3678.56) v1@4085.24,3669.36 ; v1(4092.2,3662.4) v1@4600.27,3662.4 ; v1@4099.16,3655.44 cw(c4115.97,3638.64) 4115.97,3662.4 cw(c4115.97,3686.16) v1@4099.16,3669.36 ; 4567.97,3662.4 cw(c4567.97,3625.33) v1@4594.18,3651.54 ; v1@4606.61,3819.96 5124.25,3819.96 5195.43,3748.78 5195.43,3406.57 5150.47,3361.61 v1(4990.83,3361.61) 4988.35,3364.09 v1(4855.79,3364.09) ; v1@4609.68,3810.52 cw(c4632.47,3787.73) 4632.47,3819.96 ; v1@4609.68,3824.44 ccw(c4620.49,3835.25) 4620.49,3819.96 ; v1@4862.75,3357.13 cw(c4879.55,3340.33) 4879.55,3364.09 cw(c4879.55,3387.86) v1@4862.75,3371.05 ; 4961.08,3364.09 cw(c4961.08,3331.86) v1@4983.87,3354.65 ; 4973.05,3364.09 ccw(c4973.05,3379.39) v1@4983.87,3368.57 ; v1@4997.79,3354.65 cw(c5014.59,3337.85) 5014.59,3361.61 cw(c5014.59,3385.38) v1@4997.79,3368.57
  other v1: 2585.51,3024.92 2794.21,3026.53 3281.73,3111.14 3722.09,3691.73 4602.72,3817.48
SEG7: 1G.1 2G.1 3G.1 4G.1 5G.1 6G.1 7G.1 8G.1 U1.15 | length 5443.9
  Top Layer w11.81: 4G.1@2647.33,2771.57 ccw(c2630.53,2788.37) 2654.29,2788.37 ccw(c2678.05,2788.37) 4G.1@2661.25,2771.57 ; v1@2647.84,2795.48 cw(c2632.28,2779.91) 4G.1@2654.29,2779.91 ; 4G.1@2654.29,2764.61 v1@2654.29,2799.96 ; 4G.1@2654.29,2777.44 cw(c2679.8,2777.44) v1@2661.76,2795.48 ; v1@2858.75,2795.56 cw(c2840.14,2776.95) 5G.1@2866.46,2776.95 ; 5G.1@2859.5,2771.96 ccw(c2842.69,2788.76) 2866.45,2788.76 ccw(c2890.22,2788.76) 5G.1@2873.42,2771.96 ; 5G.1@2866.46,2765 v1@2866.46,2801.77 ; 5G.1@2866.46,2780.56 cw(c2887.66,2780.56) v1@2872.67,2795.56 ; v1@3485.56,3373.24 cw(c3467.71,3355.39) 3492.95,3355.39 ; 1G.1@3485.99,3329.26 cw(c3469.19,3312.46) 3492.95,3312.46 cw(c3516.71,3312.46) 1G.1@3499.91,3329.26 ; 1G.1@3485.99,3343.18 ccw(c3469.19,3359.98) 3492.95,3359.98 ccw(c3516.71,3359.98) 1G.1@3499.91,3343.18 ; 3492.95,3357.48 cw(c3515.24,3357.48) v1@3499.48,3373.24 ; v1@3492.95,3378.35 1G.1@3492.95,3336.22 3492.95,3178.78 3541.5,3130.24 v1(3541.5,2801.97) ; v1@3534.54,2808.93 ccw(c3517.73,2825.73) 3541.49,2825.73 ccw(c3565.26,2825.73) v1@3548.46,2808.93 ; 2G.1@3856.03,3343.18 ccw(c3839.23,3359.98) 3862.99,3359.98 ccw(c3886.75,3359.98) 2G.1@3869.95,3343.18 ; v1@3856.78,3372.37 cw(c3841.78,3357.37) 3862.99,3357.37 ; 2G.1@3862.99,3336.22 v1@3862.99,3378.58 ; 3862.99,3353.76 cw(c3889.31,3353.76) v1@3870.7,3372.37 ; 3G.1@4226.11,3343.18 ccw(c4209.31,3359.98) 4233.07,3359.98 ccw(c4256.83,3359.98) 3G.1@4240.03,3343.18 ; v1@4226.5,3374.14 cw(c4210.65,3358.29) 4233.07,3358.29 ; 3G.1@4233.07,3336.22 v1@4233.07,3380.71 ; 4233.07,3356.39 cw(c4258.18,3356.39) v1@4240.42,3374.14 ; v1@4651.9,2794.85 cw(c4633.39,2776.34) 6G.1@4659.57,2776.34 ; 6G.1@4652.61,2771.37 ccw(c4635.8,2788.17) 4659.57,2788.17 ccw(c4683.33,2788.17) 6G.1@4666.53,2771.37 ; 6G.1@4659.57,2764.41 v1@4659.57,2801.1 ; 6G.1@4659.57,2779.76 cw(c4680.91,2779.76) v1@4665.82,2794.85 ; v1@4864.89,2795.52 cw(c4847.42,2778.05) 7G.1@4872.12,2778.05 ; 7G.1@4865.17,2771.57 ccw(c4848.36,2788.37) v1@4872.12,2788.37 ; 7G.1@4872.12,2764.61 v1@4872.12,2802.2 ; 7G.1@4872.13,2779.38 cw(c4894.95,2779.38) v1@4878.81,2795.52 ; v1@4872.13,2788.37 ccw(c4895.89,2788.37) 7G.1@4879.09,2771.57 ; v1@5059.17,2802.25 cw(c5021.33,2764.41) 8G.1@5074.84,2764.41 ; v1@5059.65,2791.93 cw(c5059.65,2768.17) 5076.45,2784.97 cw(c5093.25,2801.77) v1@5069.49,2801.77 ; v1(5059.65,2801.77) 5084.68,2776.73 8G.1@5084.68,2764.41 ; 5079.33,2782.08 cw(c5061.65,2764.41) 8G.1@5086.65,2764.41
  Bottom Layer w11.81: v1(2654.8,2802.44) v1@3535.04,2802.44 ; v1@2661.76,2795.48 cw(c2678.57,2778.68) 2678.57,2802.44 cw(c2678.57,2826.2) v1@2661.76,2809.4 ; 2841.76,2802.44 ccw(c2841.76,2826.47) v1@2858.75,2809.48 ; 2842.14,2802.44 cw(c2842.14,2778.95) v1@2858.75,2795.56 ; v1@2872.67,2795.56 cw(c2889.28,2778.95) 2889.28,2802.44 ; v1@2872.67,2809.48 ccw(c2889.66,2826.47) 2889.66,2802.44 ; v1@3485.56,3387.16 ccw(c3469.71,3403.01) 3492.12,3403.01 ; U1.15@3487.82,3457.37 cw(c3477.41,3446.97) 3492.12,3446.97 ; v1@3492.13,3380.59 U1.15@3492.13,3489.68 ; 3492.13,3404.91 ccw(c3517.23,3404.91) 3499.48,3387.16 ccw(c3516.28,3403.96) 3516.28,3380.2 ccw(c3516.28,3356.43) v1@3499.48,3373.24 ; 3492.13,3446.97 cw(c3506.84,3446.97) U1.15@3496.44,3457.37 ; v1(3492.52,3380.2) v1@4233.27,3380.2 ; 3516.59,2802.44 cw(c3516.59,2777.07) v1@3534.54,2795.01 ; 3518.87,2802.44 ccw(c3518.87,2824.59) v1@3534.54,2808.93 ; v1(3541.5,2801.97) 3732.87,2801.97 3788.31,2857.4 3854.13,2857.4 3939.61,2771.93 4150.35,2771.93 4184.76,2806.34 v1@5062.13,2806.34 ; v1@3548.46,2795.01 cw(c3565.26,2778.21) 3565.26,2801.97 cw(c3565.26,2825.73) v1@3548.46,2808.93 ; 3837.89,3380.19 cw(c3837.89,3353.48) v1@3856.78,3372.37 ; 3842.07,3380.2 ccw(c3842.07,3401) v1@3856.78,3386.29 ; v1@3870.7,3372.37 cw(c3889.59,3353.48) 3889.59,3380.19 ; v1@3870.7,3386.29 ccw(c3885.41,3401) 3885.41,3380.2 ; 4207.52,3380.2 ccw(c4207.52,3407.05) v1@4226.5,3388.06 ; 4211.89,3380.2 cw(c4211.89,3359.53) v1@4226.5,3374.14 ; 4624.16,2806.34 cw(c4624.16,2767.12) v1@4651.9,2794.85 ; v1@4665.82,2794.85 cw(c4693.55,2767.12) 4693.55,2806.34 ; 4838.77,2806.34 cw(c4838.77,2769.4) v1@4864.89,2795.52 ; v1@4878.81,2795.52 cw(c4904.93,2769.4) 4904.93,2806.34 ; 5024.86,2806.34 cw(c5024.86,2766.98) v1@5052.69,2794.81
  other v1: 4658.86,2801.81 4871.85,2802.48 2865.71,2802.52 3863.74,3379.33 4233.46,3381.1
SEG8: 1H1.1 1H.1 2H1.1 2H.1 3H1.1 3H.1 4H1.1 4H.1 5H1.1 5H.1 6H1.1 6H.1 7H1.1 7H.1 8H.1 U1.16 | length 8132.8
  Top Layer w11.81: 1H.1@2925.68,3143.95 ccw(c2908.88,3127.15) 2908.88,3150.91 ccw(c2908.88,3174.67) 1H.1@2925.68,3157.87 ; 1H.1@2932.64,3150.91 2901.02,3150.91 2883.23,3168.7 2883.23,3331.85 2903.3,3351.93 2942.35,3351.93 ; 1H1.1@2977.09,3344.97 ccw(c2960.29,3328.16) 2960.29,3351.93 ccw(c2960.29,3375.69) 1H1.1@2977.09,3358.89 ; 1H1.1@2984.05,3351.93 2942.35,3351.93 ; 2984.03,3574.77 ccw(c2984.03,3592.19) v1@2996.35,3579.87 ; v1@2995.74,3566.62 ccw(c2978.35,3552.15) 2978.35,3574.77 ; v1@3010.27,3565.95 cw(c3031.55,3544.67) 3031.55,3574.77 ; v1@3010.27,3579.87 ccw(c3022.59,3592.19) 3022.59,3574.77 ; 2H.1@3111.73,3567.81 ccw(c3094.93,3551.01) 3094.93,3574.77 ccw(c3094.93,3598.53) 2H.1@3111.73,3581.73 ; 2H.1@3118.69,3574.77 3073.91,3574.77 ; 2H1.1@3257.44,3709.11 ccw(c3240.64,3692.31) 3240.64,3716.07 ccw(c3240.64,3739.83) 2H1.1@3257.44,3723.03 ; 2H1.1@3264.4,3716.07 3210.51,3716.07 ; 8H.1@3455.99,2250.64 cw(c3439.19,2233.84) 3462.95,2233.84 cw(c3486.71,2233.84) 8H.1@3469.91,2250.64 ; 8H.1@3462.95,2257.6 3462.95,2212.13 3478.62,2196.46 4207.13,2196.46 4372.24,2361.57 v1(4372.24,3468.27) 4372.24,3578.78 4345.51,3605.51 4345.51,3739.69 ; 3H.1@3480.53,3833.8 ccw(c3463.73,3817) 3463.73,3840.76 ccw(c3463.73,3864.52) 3480.53,3847.72 ccw(c3463.73,3864.52) 3487.49,3864.52 ccw(c3511.25,3864.52) 3H.1@3494.45,3847.72 ; 3H1.1@3671.98,3902.29 ccw(c3655.18,3919.09) 3678.94,3919.09 ccw(c3702.7,3919.09) 3H1.1@3685.9,3902.29 ; 3H1.1@3678.94,3895.32 3678.94,3959.41 ; 7H.1@3805.44,2250.64 cw(c3788.64,2233.84) 3812.4,2233.84 cw(c3836.16,2233.84) 7H.1@3819.36,2250.64 ; 3812.4,2197.76 7H.1@3812.4,2257.6 ; 4H.1@3926.75,3910.5 ccw(c3909.94,3927.3) 3933.7,3927.3 ccw(c3957.47,3927.3) 4H.1@3940.67,3910.5 ; 4H.1@3933.71,3903.54 3933.71,3962.55 ; 7H1.1@4014.3,2250.56 cw(c3997.5,2233.76) 4021.26,2233.76 cw(c4045.02,2233.76) 7H1.1@4028.22,2250.56 ; 4021.26,2197.6 7H1.1@4021.26,2257.52 ; 4H1.1@4121.38,3872.71 ccw(c4104.58,3889.51) 4128.34,3889.51 ccw(c4152.11,3889.51) 4H1.1@4135.3,3872.71 ; 4H1.1@4128.34,3865.75 4128.34,3963.66 ; 4345.51,3694.65 cw(c4420.64,3694.65) 5H.1@4367.52,3747.77 ; 4345.51,3723.16 cw(c4392.13,3723.16) 5H.1@4359.17,3756.12 ; 5H.1@4350.75,3753.94 cw(c4332.73,3752.47) 4345.51,3739.69 ; 5H.1@4353.6,3761.69 ccw(c4336.8,3778.49) 4360.56,3778.49 ccw(c4384.32,3778.49) 5H.1@4367.52,3761.69 ; 5H.1@4359.76,3744.92 ccw(c4358.29,3726.91) 4345.51,3739.69 ; 4360.56,3960.86 5H.1@4360.56,3754.73 4345.51,3739.69 ; v1@4365.28,3461.31 cw(c4348.48,3444.51) 4372.24,3444.51 cw(c4396.01,3444.51) v1@4379.2,3461.31 ; v1@4365.28,3475.23 ccw(c4348.48,3492.03) 4372.24,3492.03 ccw(c4396.01,3492.03) v1@4379.2,3475.23 ; 5H1.1@4511.12,3631.15 ccw(c4494.31,3647.95) 4518.08,3647.95 ccw(c4541.84,3647.95) 5H1.1@4525.04,3631.15 ; 5H1.1@4518.08,3624.18 4518.08,3886.96 4441.1,3963.94 3534.72,3963.94 3487.49,3916.7 3H.1@3487.49,3840.76 3242.13,3840.76 3210.51,3809.15 3210.51,3716.07 ; v1@4627.13,3461.81 cw(c4627.13,3419.61) 4656.97,3449.45 ; v1@4629.65,3476.77 4666.04,3440.38 6H.1@4666.04,3410.07 4667.1,3411.13 4720.93,3411.13 4732.96,3399.09 6H1.1@4732.96,3213.3 ; 6H.1@4659.08,3417.03 ccw(c4642.28,3433.83) 4666.04,3433.83 ccw(c4689.8,3433.83) 4673,3417.03 ccw(c4687.24,3431.27) 4687.24,3411.13 ; 6H.1@4673,3403.11 cw(c4692.36,3383.74) 4692.36,3411.13 ; 6H1.1@4726,3220.27 ccw(c4709.2,3237.07) 4732.96,3237.07 ccw(c4756.73,3237.07) 6H1.1@4739.92,3220.27 ; 2942.35,3351.93 2942.35,3538.77 2978.35,3574.77 ; 2978.35,3574.77 3073.91,3574.77 ; 3073.91,3574.77 3073.91,3704.97 3085.01,3716.07 3210.51,3716.07
  Bottom Layer w11.81: v1@3003.54,3572.44 3434.42,3572.44 3530.63,3572.44 3542.13,3560.94 U1.16@3542.13,3489.68 ; v1@3010.27,3565.95 cw(c3025.93,3550.29) 3025.93,3572.44 ; v1@3010.27,3579.87 ccw(c3028.21,3597.82) 3028.21,3572.44 ; U1.16@3537.82,3521.99 ccw(c3527.41,3532.4) 3542.12,3532.4 ; 3542.13,3532.4 ccw(c3556.84,3532.4) U1.16@3546.44,3521.99 ; v1@4375.63,3471.65 4460.87,3471.65 ; v1@4379.2,3461.31 cw(c4404.18,3436.33) 4404.18,3471.65 ; v1@4379.2,3475.23 ccw(c4387.83,3483.86) 4387.83,3471.65 ; 4432.64,3471.65 4460.87,3471.65 ; v1@4620.17,3464.69 ccw(c4603.36,3447.89) 4603.36,3471.65 ccw(c4603.36,3495.41) v1@4620.17,3478.61 ; v1(4627.13,3471.65) 4460.87,3471.65
  other v1: 3003.31,3572.91
pads on no net: U1.1 U1.3 U1.5 U1.19 U1.21 U1.23 U1.25 U1.27 U2.9

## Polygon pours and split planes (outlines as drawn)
no net on Top Overlay (hatched 90Degree grid 0 track 7.87, remove dead copper): 0,0
no net on Top Overlay (hatched 90Degree grid 0 track 7.87, remove dead copper): 0,0
no net on Top Overlay (hatched 90Degree grid 0 track 7.87, remove dead copper): 0,0
no net on Top Overlay (hatched 90Degree grid 0 track 7.87, remove dead copper): 0,0
no net on Top Overlay (hatched 90Degree grid 0 track 7.87, remove dead copper): 0,0
no net on Top Overlay (hatched 90Degree grid 0 track 7.87, remove dead copper): 0,0

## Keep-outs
Keep-Out Layer:
  circle w0.04: c4773.93,2448.69 r31.5
  circle w0.04: c3834.39,3734.41 r31.5
  circle w0.04: c5020.11,3435.16 r31.5
  circle w0.04: c3834.39,2780.93 r31.5
  circle w0.04: c2589.35,2401.95 r31.5
  circle w0.04: c3068.71,3085.45 r31.5
  circle w0.04: c2589.35,3549.14 r31.5
  circle w0.04: c5617.16,2320.11 r59.05
  circle w0.04: c5617,3786.72 r59.05
  circle w0.04: c2051.7,2319.91 r59.05
  circle w0.04: c2051.7,3786.52 r59.05
  lines w0.04: 1905.25,2101.19 5763.63,2101.19 5763.41,4069.7 1905.25,4069.7 1905.25,2101.19 ; 2141.05,2632.84 2219.79,2632.84 2219.79,2829.7 2141.05,2829.7 2141.05,2632.84 ; 2141.05,3286.47 2219.79,3286.47 2219.79,3483.32 2141.05,3483.32 2141.05,3286.47 ; 5448.95,3286.66 5448.93,3483.51 5527.67,3483.51 5527.69,3286.66 5448.95,3286.66 ; 5449.01,2829.88 5527.74,2829.89 5527.77,2633.04 5449.03,2633.03 5449.01,2829.88

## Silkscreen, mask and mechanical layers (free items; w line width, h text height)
Top Overlay:
  region: 3383.82,3827.51 3372.65,3820.73 3407.32,3763.66 3418.49,3770.45
  region: 3028.99,3504.09 3023.43,3492.26 3083.86,3463.86 3089.42,3475.69
  region: 4718.27,3063 4718.3,3049.93 4785.07,3050.08 4785.04,3063.15
  region: 4573.08,3498.58 4578.96,3486.91 4638.6,3516.95 4632.72,3528.62
  region: 4237.95,3777.64 4249.37,3771.27 4281.88,3829.6 4270.46,3835.96
  rectangle: 3818.35,3874.96 3831.42,3941.73
  rectangle: 5226.53,2565.32 5330.9,2707.68
  rectangle: 4986.81,3557.4 5161.81,3752.01
  rectangle: 3016.81,2572.16 3117.64,2698.82
  rectangle: 3773.23,2858.39 3906.18,2986.81
  rectangle: 3698.62,2200.67 4071.85,2311.53
  rectangle: 3303.03,2201.69 3558.31,2311.53
  rectangle: 2474.41,3651.34 2715.55,3756.73
  text "7f14" at 5116.14,2864.17 h60 r90
  text "7f 08" at 2893.7,2218.5 h60 r90
Bottom Overlay:
  text "XH-8050AB" at 3082.4,3254.21 h47.24
  text "SCLK" at 3960.59,2577.09 h39.37 r270
  text "DIN" at 3862.72,2574.84 h39.37 r270
  text "GND" at 3759.57,2571.34 h39.37 r270
  text "15V" at 3643.5,2566.89 h39.37 r270
Mechanical 1:
  drawing of 2868 lines, arcs and shapes, not listed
